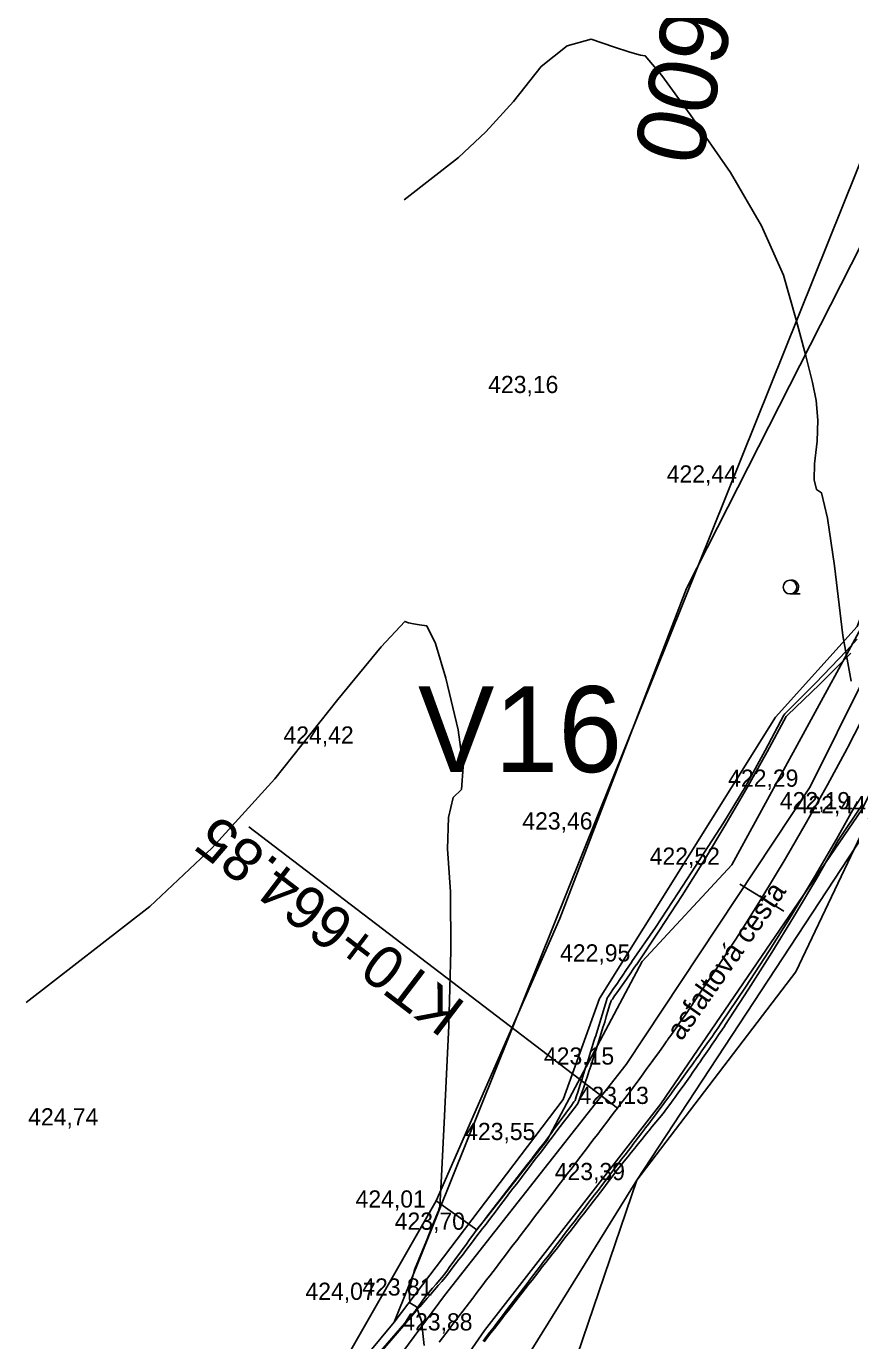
# Model space of a CAD drawing. Extents: x -574342 to -507939, y -1144044 to -1123894.
# Drawn here: x -508562.3 to -508514.3, y -1143703.9 to -1143627.4 of the extents above; entities that cross this region are included whole.
import ezdxf

# ---------------------------------------------------------------- set-up
doc = ezdxf.new("R2010")
doc.units = 0
for name, color, linetype in [('01_PARCELY_NAVRH_PC', 7, 'Continuous'), ('01_PARCELY_NAVRH_ŽP', 7, 'Continuous'), ('03_PC_OBJEKTY_POP_NAVRH', 7, 'Continuous'), ('1000', 7, 'Continuous'), ('15', 7, 'Continuous'), ('18', 7, 'Continuous'), ('21', 7, 'Continuous'), ('23', 7, 'Continuous'), ('37', 7, 'Continuous'), ('42', 7, 'Continuous'), ('43', 7, 'Continuous'), ('55', 7, 'Continuous'), ('6', 7, 'Continuous'), ('Level 255', 7, 'Continuous'), ('VRST VEDL', 7, 'Continuous')]:
    doc.layers.add(name, color=color, linetype=linetype)

msp = doc.modelspace()

# ---------------------------------------------------------------- linework, layer by layer
at = {"layer": '01_PARCELY_NAVRH_PC'}
for points in [[(-508550.74, -1143812.56), (-508547.51, -1143799.72), (-508547.8, -1143787.43), (-508554.08, -1143749.16), (-508553.41, -1143747.02), (-508554.21, -1143734.12), (-508553.55, -1143725.9), (-508551.64, -1143719.89), (-508547.57, -1143710.87), (-508540.84, -1143702.78), (-508531.01, -1143689.84), (-508528.88, -1143683.95), (-508518.64, -1143667.59), (-508513.88, -1143662.3), (-508507.94, -1143646.93), (-508502.84, -1143629.47), (-508500.33, -1143614.14), (-508495.09, -1143559.2), (-508493.85, -1143537.59)], [(-508550.74, -1143812.56), (-508547.51, -1143799.72), (-508547.8, -1143787.43), (-508554.08, -1143749.16), (-508553.41, -1143747.02), (-508554.21, -1143734.12), (-508553.55, -1143725.9), (-508551.64, -1143719.89), (-508547.57, -1143710.87), (-508540.84, -1143702.78), (-508531.01, -1143689.84), (-508528.88, -1143683.95), (-508518.64, -1143667.59), (-508513.88, -1143662.3), (-508507.94, -1143646.93), (-508502.84, -1143629.47), (-508500.33, -1143614.14), (-508495.09, -1143559.2), (-508493.85, -1143537.59)], [(-508488.59, -1143541.43), (-508489.82, -1143560.44), (-508491.6, -1143582.01), (-508495.73, -1143620.81), (-508499.42, -1143638.98), (-508505.75, -1143657.81), (-508517.46, -1143682.4), (-508526.71, -1143694.52), (-508540.76, -1143717.14), (-508543.32, -1143721.09), (-508546.79, -1143736.35), (-508545.73, -1143746.01), (-508540.36, -1143791.5), (-508536.1, -1143827.99)], [(-508488.59, -1143541.43), (-508489.82, -1143560.44), (-508491.6, -1143582.01), (-508495.73, -1143620.81), (-508499.42, -1143638.98), (-508505.75, -1143657.81), (-508517.46, -1143682.4), (-508526.71, -1143694.52), (-508540.76, -1143717.14), (-508543.32, -1143721.09), (-508546.79, -1143736.35), (-508545.73, -1143746.01), (-508540.36, -1143791.5), (-508536.1, -1143827.99)]]:
    msp.add_lwpolyline(points, dxfattribs=at)
at = {"layer": '01_PARCELY_NAVRH_ŽP'}
msp.add_lwpolyline([(-508493.85, -1143537.59), (-508495.09, -1143559.2), (-508500.33, -1143614.14), (-508502.84, -1143629.47), (-508507.94, -1143646.93), (-508513.88, -1143662.3), (-508518.64, -1143667.59), (-508528.88, -1143683.95), (-508531.01, -1143689.84), (-508540.84, -1143702.78), (-508502.09, -1143606.43), (-508497.34, -1143500.64)], dxfattribs=at)
at = {"layer": '1000'}
for points in [[(-508513.873, -1143663.045), (-508514.517, -1143663.734), (-508516.289, -1143665.585), (-508518.086, -1143667.395), (-508518.155, -1143667.462), (-508519.244, -1143669.526), (-508520.408, -1143671.655), (-508521.665, -1143673.73), (-508522.992, -1143675.762), (-508523.051, -1143675.857), (-508524.299, -1143677.803), (-508525.637, -1143679.824), (-508527.007, -1143681.807), (-508527.014, -1143681.818), (-508527.182, -1143682.069), (-508527.357, -1143682.331), (-508527.533, -1143682.592), (-508527.71, -1143682.853), (-508527.886, -1143683.114), (-508528.064, -1143683.374), (-508528.241, -1143683.634), (-508528.373, -1143683.825), (-508528.42, -1143683.894), (-508528.447, -1143683.934), (-508528.527, -1143684.204), (-508528.623, -1143684.524), (-508528.719, -1143684.843), (-508528.816, -1143685.163), (-508528.913, -1143685.483), (-508529.011, -1143685.803), (-508529.11, -1143686.123), (-508529.153, -1143686.26), (-508529.21, -1143686.443), (-508529.31, -1143686.763), (-508529.411, -1143687.083), (-508529.513, -1143687.403), (-508529.615, -1143687.724), (-508529.718, -1143688.044), (-508529.82, -1143688.366), (-508529.923, -1143688.688), (-508529.936, -1143688.727), (-508530.029, -1143689.013), (-508530.136, -1143689.34), (-508530.242, -1143689.667), (-508530.312, -1143689.882), (-508530.377, -1143689.971), (-508530.568, -1143690.233), (-508530.759, -1143690.496), (-508530.95, -1143690.758), (-508531.141, -1143691.02), (-508531.332, -1143691.282), (-508531.523, -1143691.545), (-508531.713, -1143691.807), (-508531.903, -1143692.07), (-508532.097, -1143692.33), (-508532.297, -1143692.586), (-508532.496, -1143692.841), (-508532.695, -1143693.097), (-508532.894, -1143693.353), (-508533.093, -1143693.609), (-508533.292, -1143693.865), (-508533.491, -1143694.121), (-508533.69, -1143694.378), (-508533.889, -1143694.634), (-508534.087, -1143694.89), (-508534.286, -1143695.147), (-508534.484, -1143695.403), (-508534.683, -1143695.659), (-508534.881, -1143695.916), (-508535.079, -1143696.173), (-508535.278, -1143696.429), (-508535.476, -1143696.686), (-508535.674, -1143696.943), (-508535.872, -1143697.199), (-508536.068, -1143697.457), (-508536.26, -1143697.719), (-508536.451, -1143697.981), (-508536.643, -1143698.243), (-508536.834, -1143698.505), (-508537.025, -1143698.767), (-508537.216, -1143699.029), (-508537.407, -1143699.291), (-508537.598, -1143699.553), (-508537.789, -1143699.815), (-508537.923, -1143699.999), (-508537.984, -1143700.074), (-508538.195, -1143700.321), (-508538.406, -1143700.568), (-508538.617, -1143700.815), (-508538.828, -1143701.062), (-508539.039, -1143701.309), (-508539.224, -1143701.575), (-508539.407, -1143701.843), (-508539.6, -1143702.104), (-508539.812, -1143702.351), (-508540.023, -1143702.597), (-508540.235, -1143702.843), (-508544.388, -1143707.644)], [(-508514.25, -1143663.864), (-508516.083, -1143665.689), (-508517.94, -1143667.472), (-508518.01, -1143667.538), (-508519.118, -1143669.596), (-508520.303, -1143671.715), (-508521.524, -1143673.814), (-508522.779, -1143675.893), (-508522.837, -1143675.988), (-508524.068, -1143677.951), (-508525.392, -1143679.986), (-508526.742, -1143681.989), (-508526.75, -1143682), (-508526.921, -1143682.249), (-508527.1, -1143682.509), (-508527.28, -1143682.768), (-508527.461, -1143683.027), (-508527.642, -1143683.285), (-508527.823, -1143683.543), (-508528.006, -1143683.801), (-508528.14, -1143683.991), (-508528.188, -1143684.058), (-508528.217, -1143684.098), (-508528.297, -1143684.369), (-508528.394, -1143684.688), (-508528.491, -1143685.008), (-508528.588, -1143685.328), (-508528.687, -1143685.647), (-508528.787, -1143685.967), (-508528.887, -1143686.287), (-508528.93, -1143686.424), (-508528.988, -1143686.606), (-508529.09, -1143686.926), (-508529.193, -1143687.245), (-508529.297, -1143687.565), (-508529.401, -1143687.884), (-508529.507, -1143688.204), (-508529.613, -1143688.523), (-508529.72, -1143688.843), (-508529.733, -1143688.882), (-508529.83, -1143689.165), (-508529.941, -1143689.489), (-508530.051, -1143689.812), (-508530.124, -1143690.025), (-508530.191, -1143690.113), (-508530.388, -1143690.371), (-508530.584, -1143690.629), (-508530.781, -1143690.887), (-508530.978, -1143691.145), (-508531.174, -1143691.403), (-508531.371, -1143691.66), (-508531.567, -1143691.918), (-508531.764, -1143692.176), (-508531.961, -1143692.434), (-508532.157, -1143692.692), (-508532.354, -1143692.95), (-508532.55, -1143693.208), (-508532.747, -1143693.465), (-508532.944, -1143693.723), (-508533.14, -1143693.981), (-508533.337, -1143694.239), (-508533.533, -1143694.497), (-508533.73, -1143694.755), (-508533.927, -1143695.013), (-508534.123, -1143695.271), (-508534.32, -1143695.528), (-508534.516, -1143695.786), (-508534.713, -1143696.044), (-508534.909, -1143696.302), (-508535.106, -1143696.56), (-508535.303, -1143696.818), (-508535.499, -1143697.076), (-508535.696, -1143697.334), (-508535.892, -1143697.591), (-508536.089, -1143697.849), (-508536.286, -1143698.107), (-508536.482, -1143698.365), (-508536.679, -1143698.623), (-508536.875, -1143698.881), (-508537.072, -1143699.139), (-508537.269, -1143699.397), (-508537.465, -1143699.654), (-508537.662, -1143699.912), (-508537.799, -1143700.093), (-508537.863, -1143700.167), (-508538.075, -1143700.413), (-508538.287, -1143700.659), (-508538.499, -1143700.905), (-508538.711, -1143701.151), (-508538.923, -1143701.397), (-508539.135, -1143701.643), (-508539.347, -1143701.889), (-508539.56, -1143702.135), (-508539.772, -1143702.381), (-508539.984, -1143702.627), (-508540.196, -1143702.873), (-508544.339, -1143707.682)], [(-508513.857, -1143672.481), (-508515.091, -1143674.688), (-508516.362, -1143676.873), (-508517.669, -1143679.037), (-508517.73, -1143679.136), (-508519.011, -1143681.179), (-508520.389, -1143683.299), (-508521.795, -1143685.384), (-508521.802, -1143685.395), (-508521.981, -1143685.654), (-508522.168, -1143685.925), (-508522.355, -1143686.195), (-508522.543, -1143686.464), (-508522.731, -1143686.733), (-508522.921, -1143687.002), (-508523.11, -1143687.27), (-508523.25, -1143687.468), (-508523.301, -1143687.538), (-508523.33, -1143687.579), (-508523.491, -1143687.806), (-508523.683, -1143688.073), (-508523.875, -1143688.339), (-508524.067, -1143688.606), (-508524.261, -1143688.871), (-508524.454, -1143689.137), (-508524.649, -1143689.402), (-508524.732, -1143689.516), (-508524.843, -1143689.666), (-508525.039, -1143689.93), (-508525.235, -1143690.194), (-508525.432, -1143690.457), (-508525.629, -1143690.72), (-508525.826, -1143690.983), (-508526.025, -1143691.245), (-508526.224, -1143691.506), (-508526.248, -1143691.539), (-508526.421, -1143691.765), (-508526.617, -1143692.023), (-508526.814, -1143692.28), (-508526.943, -1143692.45), (-508527.01, -1143692.538), (-508527.207, -1143692.796), (-508527.403, -1143693.054), (-508527.6, -1143693.312), (-508527.797, -1143693.57), (-508527.993, -1143693.828), (-508528.19, -1143694.085), (-508528.386, -1143694.343), (-508528.583, -1143694.601), (-508528.78, -1143694.859), (-508528.976, -1143695.117), (-508529.173, -1143695.375), (-508529.369, -1143695.633), (-508529.566, -1143695.891), (-508529.763, -1143696.148), (-508529.959, -1143696.406), (-508530.156, -1143696.664), (-508530.352, -1143696.922), (-508530.549, -1143697.18), (-508530.746, -1143697.438), (-508530.942, -1143697.696), (-508531.139, -1143697.954), (-508531.335, -1143698.211), (-508531.532, -1143698.469), (-508531.728, -1143698.727), (-508531.925, -1143698.985), (-508532.122, -1143699.243), (-508532.318, -1143699.501), (-508532.515, -1143699.759), (-508532.711, -1143700.017), (-508532.908, -1143700.274), (-508533.105, -1143700.532), (-508533.301, -1143700.79), (-508533.498, -1143701.048), (-508533.694, -1143701.306), (-508533.891, -1143701.564), (-508534.088, -1143701.822), (-508534.284, -1143702.079), (-508534.481, -1143702.337), (-508534.618, -1143702.518), (-508534.677, -1143702.595), (-508534.874, -1143702.853), (-508535.071, -1143703.111), (-508535.267, -1143703.369), (-508535.464, -1143703.627), (-508535.66, -1143703.885)], [(-508513.567, -1143672.64), (-508514.981, -1143674.75), (-508516.236, -1143676.948), (-508517.527, -1143679.124), (-508517.587, -1143679.224), (-508518.853, -1143681.28), (-508520.208, -1143683.419), (-508521.586, -1143685.527), (-508521.594, -1143685.538), (-508521.769, -1143685.801), (-508521.952, -1143686.074), (-508522.137, -1143686.347), (-508522.322, -1143686.619), (-508522.507, -1143686.891), (-508522.694, -1143687.162), (-508522.881, -1143687.433), (-508523.019, -1143687.632), (-508523.069, -1143687.703), (-508523.098, -1143687.745), (-508523.257, -1143687.973), (-508523.447, -1143688.242), (-508523.636, -1143688.511), (-508523.827, -1143688.78), (-508524.019, -1143689.048), (-508524.211, -1143689.315), (-508524.403, -1143689.582), (-508524.486, -1143689.697), (-508524.597, -1143689.848), (-508524.791, -1143690.114), (-508524.986, -1143690.38), (-508525.189, -1143690.639), (-508525.399, -1143690.893), (-508525.609, -1143691.147), (-508525.817, -1143691.402), (-508526.023, -1143691.659), (-508526.049, -1143691.691), (-508526.228, -1143691.912), (-508526.431, -1143692.164), (-508526.635, -1143692.416), (-508526.769, -1143692.582), (-508526.839, -1143692.669), (-508527.043, -1143692.921), (-508527.248, -1143693.173), (-508527.452, -1143693.425), (-508527.656, -1143693.677), (-508527.861, -1143693.929), (-508528.057, -1143694.187), (-508528.25, -1143694.447), (-508528.444, -1143694.707), (-508528.638, -1143694.967), (-508528.833, -1143695.226), (-508529.031, -1143695.483), (-508529.23, -1143695.739), (-508529.428, -1143695.995), (-508529.627, -1143696.252), (-508529.826, -1143696.508), (-508530.025, -1143696.764), (-508530.224, -1143697.02), (-508530.423, -1143697.276), (-508530.622, -1143697.532), (-508530.822, -1143697.788), (-508531.021, -1143698.043), (-508531.22, -1143698.299), (-508531.42, -1143698.555), (-508531.619, -1143698.81), (-508531.819, -1143699.066), (-508532.019, -1143699.321), (-508532.219, -1143699.577), (-508532.419, -1143699.832), (-508532.619, -1143700.087), (-508532.819, -1143700.342), (-508533.019, -1143700.598), (-508533.219, -1143700.853), (-508533.419, -1143701.108), (-508533.619, -1143701.364), (-508533.817, -1143701.62), (-508534.016, -1143701.876), (-508534.215, -1143702.132), (-508534.414, -1143702.388), (-508534.553, -1143702.568), (-508534.613, -1143702.645), (-508534.812, -1143702.901), (-508535.011, -1143703.156), (-508535.21, -1143703.412), (-508535.409, -1143703.668), (-508535.608, -1143703.925)]]:
    msp.add_lwpolyline(points, dxfattribs=at)
at = {"layer": '21'}
msp.add_lwpolyline([(-508513.284, -1143667.105), (-508514.429, -1143669.322), (-508514.473, -1143669.405), (-508515.61, -1143671.519), (-508516.828, -1143673.697), (-508518.082, -1143675.854), (-508519.372, -1143677.989), (-508519.432, -1143678.087), (-508520.697, -1143680.103), (-508522.057, -1143682.195), (-508523.444, -1143684.252), (-508523.451, -1143684.263), (-508523.627, -1143684.519), (-508523.812, -1143684.786), (-508523.997, -1143685.052), (-508524.182, -1143685.318), (-508524.368, -1143685.584), (-508524.555, -1143685.849), (-508524.742, -1143686.114), (-508524.88, -1143686.309), (-508524.93, -1143686.378), (-508524.959, -1143686.419), (-508525.118, -1143686.642), (-508525.307, -1143686.906), (-508525.497, -1143687.169), (-508525.687, -1143687.432), (-508525.877, -1143687.694), (-508526.068, -1143687.956), (-508526.26, -1143688.217), (-508526.343, -1143688.33), (-508526.452, -1143688.478), (-508526.645, -1143688.739), (-508526.839, -1143688.999), (-508527.033, -1143689.259), (-508527.227, -1143689.519), (-508527.423, -1143689.778), (-508527.618, -1143690.036), (-508527.814, -1143690.294), (-508527.839, -1143690.326), (-508528.011, -1143690.552), (-508528.208, -1143690.81), (-508528.404, -1143691.068), (-508528.533, -1143691.237), (-508528.601, -1143691.326), (-508528.797, -1143691.584), (-508528.994, -1143691.841), (-508529.191, -1143692.099), (-508529.387, -1143692.357), (-508529.584, -1143692.615), (-508529.78, -1143692.873), (-508529.977, -1143693.131), (-508530.174, -1143693.389), (-508530.37, -1143693.647), (-508530.567, -1143693.904), (-508530.763, -1143694.162), (-508530.96, -1143694.42), (-508531.156, -1143694.678), (-508531.353, -1143694.936), (-508531.55, -1143695.194), (-508531.746, -1143695.452), (-508531.943, -1143695.71), (-508532.139, -1143695.967), (-508532.336, -1143696.225), (-508532.533, -1143696.483), (-508532.729, -1143696.741), (-508532.926, -1143696.999), (-508533.122, -1143697.257), (-508533.319, -1143697.515), (-508533.516, -1143697.772), (-508533.712, -1143698.03), (-508533.909, -1143698.288), (-508534.105, -1143698.546), (-508534.302, -1143698.804), (-508534.499, -1143699.062), (-508534.695, -1143699.32), (-508534.892, -1143699.578), (-508535.088, -1143699.835), (-508535.285, -1143700.093), (-508535.481, -1143700.351), (-508535.678, -1143700.609), (-508535.875, -1143700.867), (-508536.071, -1143701.125), (-508536.209, -1143701.305), (-508536.268, -1143701.383), (-508536.464, -1143701.641), (-508536.661, -1143701.898), (-508536.858, -1143702.156), (-508537.054, -1143702.414), (-508537.251, -1143702.672), (-508537.447, -1143702.93), (-508537.644, -1143703.188), (-508537.841, -1143703.446), (-508538.037, -1143703.704), (-508538.234, -1143703.961)], dxfattribs=at)
at = {"layer": '23'}
for points in [[(-508527.839, -1143690.326), (-508549.311, -1143673.957)], [(-508527.839, -1143690.326), (-508530.225, -1143688.507)]]:
    msp.add_lwpolyline(points, dxfattribs=at)
at = {"layer": '37'}
for points in [[(-508525.32, -1143690.09), (-508513.6, -1143672.94), (-508505.96, -1143657.45), (-508499.97, -1143638.8), (-508496.4, -1143619.04), (-508492.34, -1143581.07), (-508490.58, -1143559.67), (-508489.7, -1143532.61), (-508489.43, -1143504.5), (-508490.15, -1143484.79), (-508492.11, -1143459.13), (-508495.1, -1143425.66), (-508500.09, -1143376.04), (-508503.8, -1143337.81), (-508507.09, -1143312.37)], [(-508525.32, -1143690.09), (-508513.6, -1143672.94), (-508505.96, -1143657.45), (-508499.97, -1143638.8), (-508496.4, -1143619.04), (-508492.34, -1143581.07), (-508490.58, -1143559.67), (-508489.7, -1143532.61), (-508489.43, -1143504.5), (-508490.15, -1143484.79), (-508492.11, -1143459.13), (-508495.1, -1143425.66), (-508500.09, -1143376.04), (-508503.8, -1143337.81), (-508507.09, -1143312.37)], [(-508510.49, -1143313.12), (-508507.27, -1143338.28), (-508503.11, -1143376.47), (-508498.08, -1143426.3), (-508495.07, -1143459.12), (-508493.11, -1143485.1), (-508492.51, -1143504.33), (-508492.91, -1143532.93), (-508493.51, -1143559.4), (-508495.57, -1143580.48), (-508499.3, -1143618.7), (-508502.79, -1143638.29), (-508508.8, -1143655.9), (-508516.61, -1143671.63), (-508527.34, -1143687.8)], [(-508510.49, -1143313.12), (-508507.27, -1143338.28), (-508503.11, -1143376.47), (-508498.08, -1143426.3), (-508495.07, -1143459.12), (-508493.11, -1143485.1), (-508492.51, -1143504.33), (-508492.91, -1143532.93), (-508493.51, -1143559.4), (-508495.57, -1143580.48), (-508499.3, -1143618.7), (-508502.79, -1143638.29), (-508508.8, -1143655.9), (-508516.61, -1143671.63), (-508527.34, -1143687.8)]]:
    msp.add_lwpolyline(points, dxfattribs=at)
at = {"layer": '42'}
for points in [[(-508504.21, -1143312.1), (-508501.69, -1143337.29), (-508498.26, -1143372.94), (-508494.88, -1143409.3), (-508491.01, -1143461.13), (-508489.31, -1143484.85), (-508488.03, -1143504.43), (-508488.95, -1143532.56), (-508489.82, -1143560.44), (-508491.6, -1143582.01), (-508495.73, -1143620.81), (-508499.42, -1143638.98), (-508505.75, -1143657.81), (-508512.68, -1143673.17), (-508526.71, -1143694.52), (-508534.28, -1143716.76), (-508532.3, -1143723.14), (-508529.03, -1143725.92)], [(-508504.21, -1143312.1), (-508501.69, -1143337.29), (-508498.26, -1143372.94), (-508494.88, -1143409.3), (-508491.01, -1143461.13), (-508489.31, -1143484.85), (-508488.03, -1143504.43), (-508488.95, -1143532.56), (-508489.82, -1143560.44), (-508491.6, -1143582.01), (-508495.73, -1143620.81), (-508499.42, -1143638.98), (-508505.75, -1143657.81), (-508512.68, -1143673.17), (-508526.71, -1143694.52), (-508534.28, -1143716.76), (-508532.3, -1143723.14), (-508529.03, -1143725.92)], [(-508538.41, -1143695.73), (-508550.7, -1143717.22), (-508554.15, -1143725.41), (-508556.26, -1143735.12)], [(-508538.41, -1143695.73), (-508550.7, -1143717.22), (-508554.15, -1143725.41), (-508556.26, -1143735.12)]]:
    msp.add_lwpolyline(points, dxfattribs=at)
msp.add_lwpolyline([(-508538.41, -1143695.73), (-508536.03, -1143697.41), (-508531.93, -1143692.19), (-508526.4, -1143681.8), (-508521.18, -1143676.17), (-508509.4, -1143654.6), (-508502.28, -1143629.22), (-508503.37, -1143624.51), (-508507.47, -1143626.62), (-508513.03, -1143638.88), (-508523.82, -1143660.09), (-508531.2, -1143679.3)], close=True, dxfattribs=at)
msp.add_lwpolyline([(-508538.41, -1143695.73), (-508536.03, -1143697.41), (-508531.93, -1143692.19), (-508526.4, -1143681.8), (-508521.18, -1143676.17), (-508509.4, -1143654.6), (-508502.28, -1143629.22), (-508503.37, -1143624.51), (-508507.47, -1143626.62), (-508513.03, -1143638.88), (-508523.82, -1143660.09), (-508531.2, -1143679.3)], close=True, dxfattribs=at)
at = {"layer": '43'}
for p, q in [((-508517.794, -1143660.412), (-508517.694, -1143660.412)), ((-508517.694, -1143660.412), (-508517.194, -1143660.412))]:
    msp.add_line(p, q, dxfattribs=at)
msp.add_circle((-508517.794, -1143660.012), 0.4, dxfattribs=at)
msp.add_arc((-508517.694, -1143660.012), 0.4, 259.69515, 97.18076, dxfattribs=at)
at = {"layer": '55'}
for points in [[(-508552.96, -1143735.51), (-508553.08, -1143725.38), (-508550.11, -1143717.7), (-508537.92, -1143701.24), (-508527.34, -1143687.8)], [(-508552.96, -1143735.51), (-508553.08, -1143725.38), (-508550.11, -1143717.7), (-508537.92, -1143701.24), (-508527.34, -1143687.8)], [(-508525.32, -1143690.09), (-508535.59, -1143703.27), (-508544.36, -1143715.94), (-508543.53, -1143722.21), (-508540.07, -1143725.98), (-508535.24, -1143727.95)], [(-508525.32, -1143690.09), (-508535.59, -1143703.27), (-508544.36, -1143715.94), (-508543.53, -1143722.21), (-508540.07, -1143725.98), (-508535.24, -1143727.95)]]:
    msp.add_lwpolyline(points, dxfattribs=at)
at = {"layer": '6'}
msp.add_lwpolyline([(-508518.155, -1143678.874), (-508520.709, -1143677.3)], dxfattribs=at)
at = {"layer": 'VRST VEDL'}
for points in [[(-508540.267, -1143637.474), (-508537.1, -1143635.016), (-508535.506, -1143633.519), (-508533.902, -1143631.754), (-508532.286, -1143629.722), (-508530.776, -1143628.515), (-508529.372, -1143628.135), (-508528.074, -1143628.581), (-508527.117, -1143628.89), (-508526.5, -1143629.062), (-508526.225, -1143629.097), (-508525.261, -1143630.246), (-508523.607, -1143632.507), (-508521.265, -1143635.882), (-508519.455, -1143638.999), (-508518.18, -1143641.86), (-508517.438, -1143644.464), (-508516.872, -1143646.549), (-508516.482, -1143648.115), (-508516.267, -1143649.163), (-508516.177, -1143650.299), (-508516.214, -1143651.526), (-508516.376, -1143652.841), (-508516.388, -1143653.78), (-508516.25, -1143654.341), (-508515.963, -1143654.526), (-508515.613, -1143656.001), (-508515.2, -1143658.767), (-508514.726, -1143662.822), (-508514.222, -1143665.483)], [(-508539.096, -1143704.155), (-508539.265, -1143702.735), (-508539.548, -1143701.905), (-508539.943, -1143701.664), (-508539.979, -1143700.942), (-508539.656, -1143699.74), (-508538.973, -1143698.058), (-508538.512, -1143696.913), (-508538.272, -1143696.305), (-508538.254, -1143696.233), (-508538.235, -1143696.171), (-508538.215, -1143696.119), (-508538.193, -1143696.077), (-508538.093, -1143694.296), (-508537.915, -1143690.775), (-508537.659, -1143685.516), (-508537.544, -1143681.175), (-508537.571, -1143677.752), (-508537.739, -1143675.248), (-508537.686, -1143673.418), (-508537.413, -1143672.264), (-508536.919, -1143671.786), (-508536.824, -1143670.468), (-508537.128, -1143668.312), (-508537.833, -1143665.316), (-508538.44, -1143663.301), (-508538.951, -1143662.267), (-508539.365, -1143662.214), (-508539.716, -1143662.154), (-508540.005, -1143662.084), (-508540.23, -1143662.007), (-508541.605, -1143663.496), (-508544.129, -1143666.552), (-508547.802, -1143671.174), (-508551.451, -1143675.187), (-508555.075, -1143678.591), (-508562.275, -1143684.179)]]:
    msp.add_lwpolyline(points, dxfattribs=at)

# ---------------------------------------------------------------- texts
at = {"layer": '03_PC_OBJEKTY_POP_NAVRH'}
msp.add_text('V16', height=5, dxfattribs=at).set_placement((-508539.467, -1143670.778))
at = {"layer": '15'}
msp.add_text('asfaltová cesta', height=1.2, rotation=55.00395, dxfattribs=at).set_placement((-508524.112, -1143686.472))
msp.add_text('asfaltová cesta', height=1.2, rotation=55.00395, dxfattribs=at).set_placement((-508524.112, -1143686.472))
at = {"layer": '18'}
for s, height, rotation, p in [('0+600', 4, 257.45196, (-508523.68, -1143620.105)), ('KT0+664.85', 2.5, 142.67945, (-508536.587, -1143684.286))]:
    msp.add_text(s, height=height, rotation=rotation, dxfattribs=at).set_placement(p)
at = {"layer": 'Level 255'}
for s, p in [('423,16', (-508535.375, -1143648.72)), ('422,44', (-508524.975, -1143653.93)), ('424,42', (-508547.295, -1143669.12)), ('422,29', (-508521.395, -1143671.63)), ('422,19', (-508518.385, -1143672.94)), ('422,44', (-508517.465, -1143673.17)), ('423,46', (-508533.385, -1143674.12)), ('422,52', (-508525.965, -1143676.17)), ('422,95', (-508531.185, -1143681.8)), ('423,15', (-508532.125, -1143687.8)), ('423,13', (-508530.105, -1143690.09)), ('424,74', (-508562.165, -1143691.34)), ('423,55', (-508536.715, -1143692.19)), ('423,39', (-508531.495, -1143694.52)), ('424,01', (-508543.095, -1143696.12)), ('423,70', (-508540.815, -1143697.41)), ('423,81', (-508542.705, -1143701.24)), ('424,07', (-508546.015, -1143701.49)), ('423,88', (-508540.375, -1143703.27))]:
    msp.add_text(s, height=1, dxfattribs=at).set_placement(p)

doc.saveas('drawing.dxf')
